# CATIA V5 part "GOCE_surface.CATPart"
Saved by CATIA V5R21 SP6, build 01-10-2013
Part number: GOCE_surface
Bounding box of the stored display mesh (mm): x -2817 to 2495.5, y -1050 to 1050, z -1218 to 1218
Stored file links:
  D:\gmarch\Desktop\GOCE\GOCE_surface.CATPart
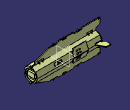
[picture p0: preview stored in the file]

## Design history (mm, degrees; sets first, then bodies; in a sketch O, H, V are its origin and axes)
Set1
  DatumSurface1
Body1 (main body)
